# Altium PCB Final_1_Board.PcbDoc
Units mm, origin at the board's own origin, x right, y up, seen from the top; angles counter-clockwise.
Board outline 30.07 x 22.07 mm, 2 copper layers (Top Layer, Bottom Layer), stack 1.671 mm thick; 36 components, 55 nets, 138 pads, 97 vias.
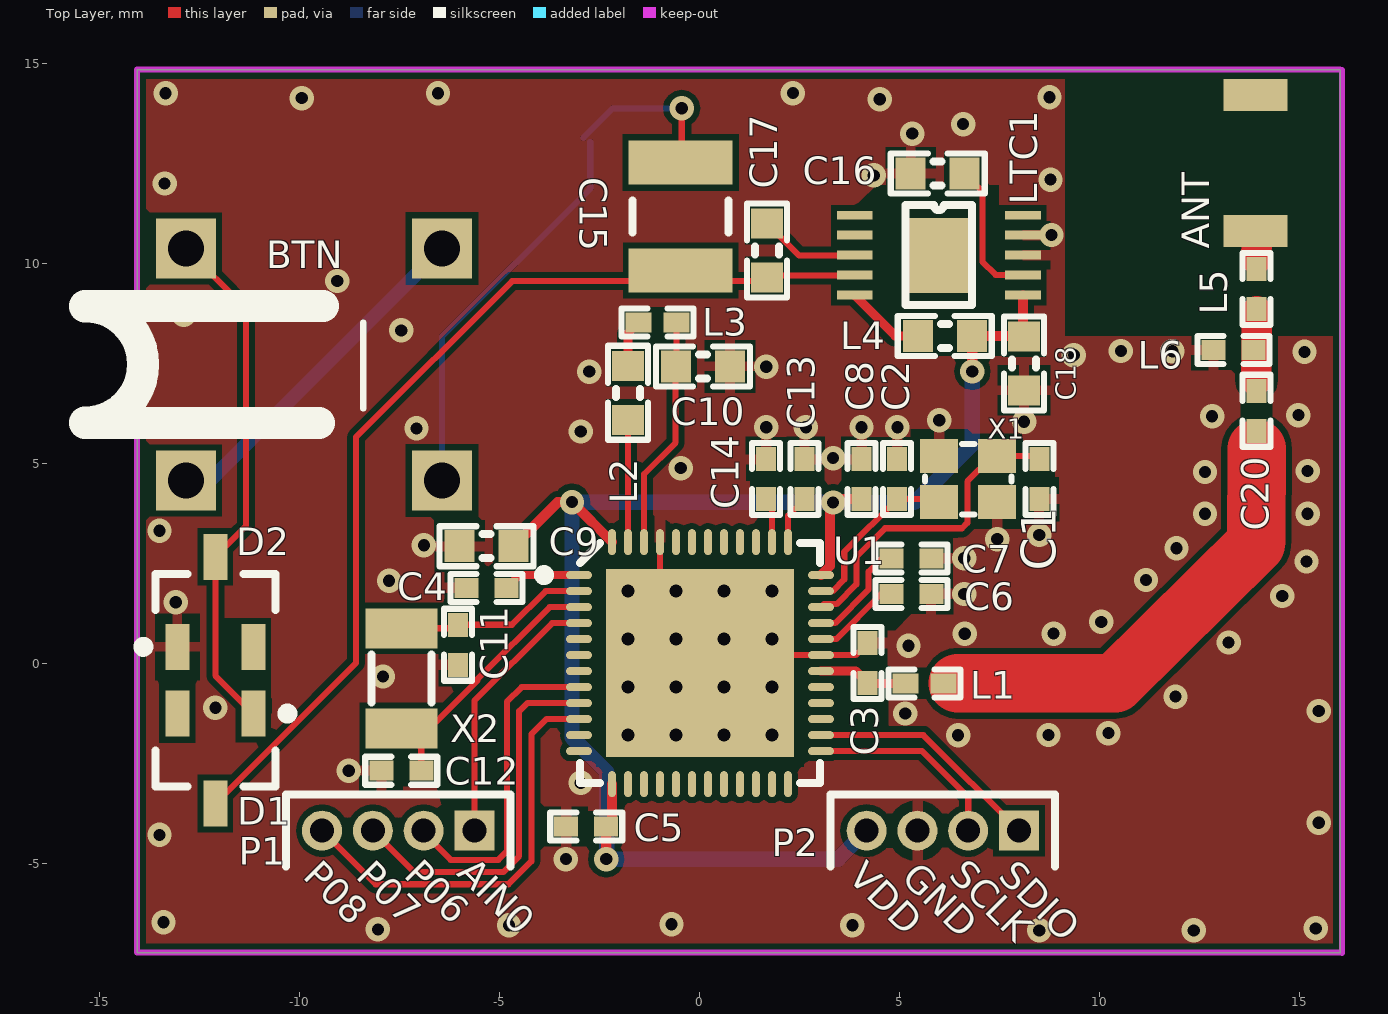
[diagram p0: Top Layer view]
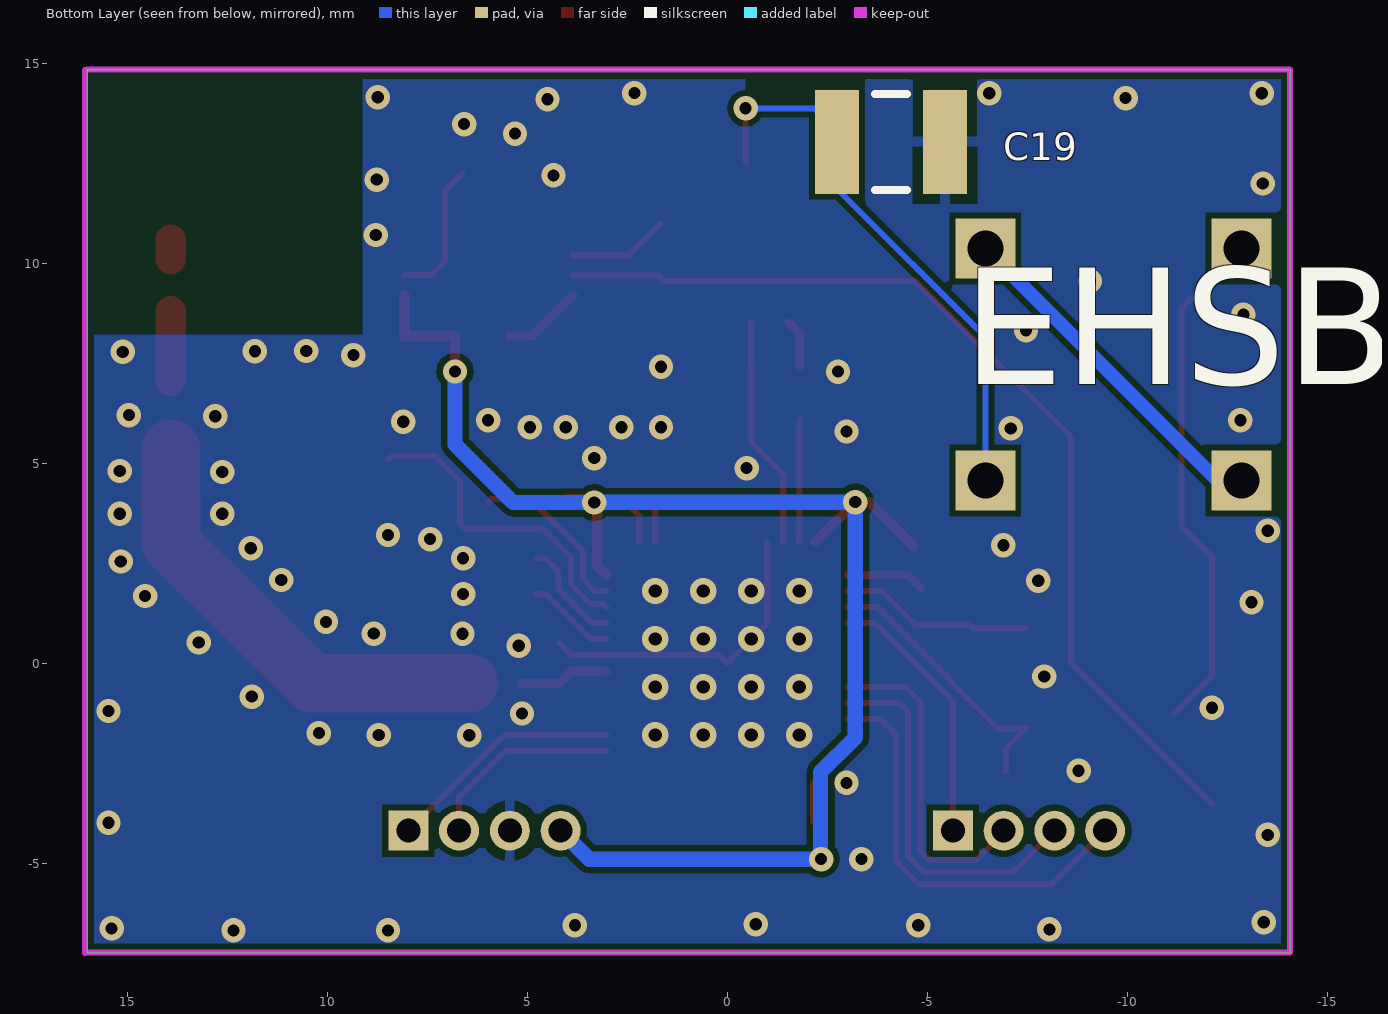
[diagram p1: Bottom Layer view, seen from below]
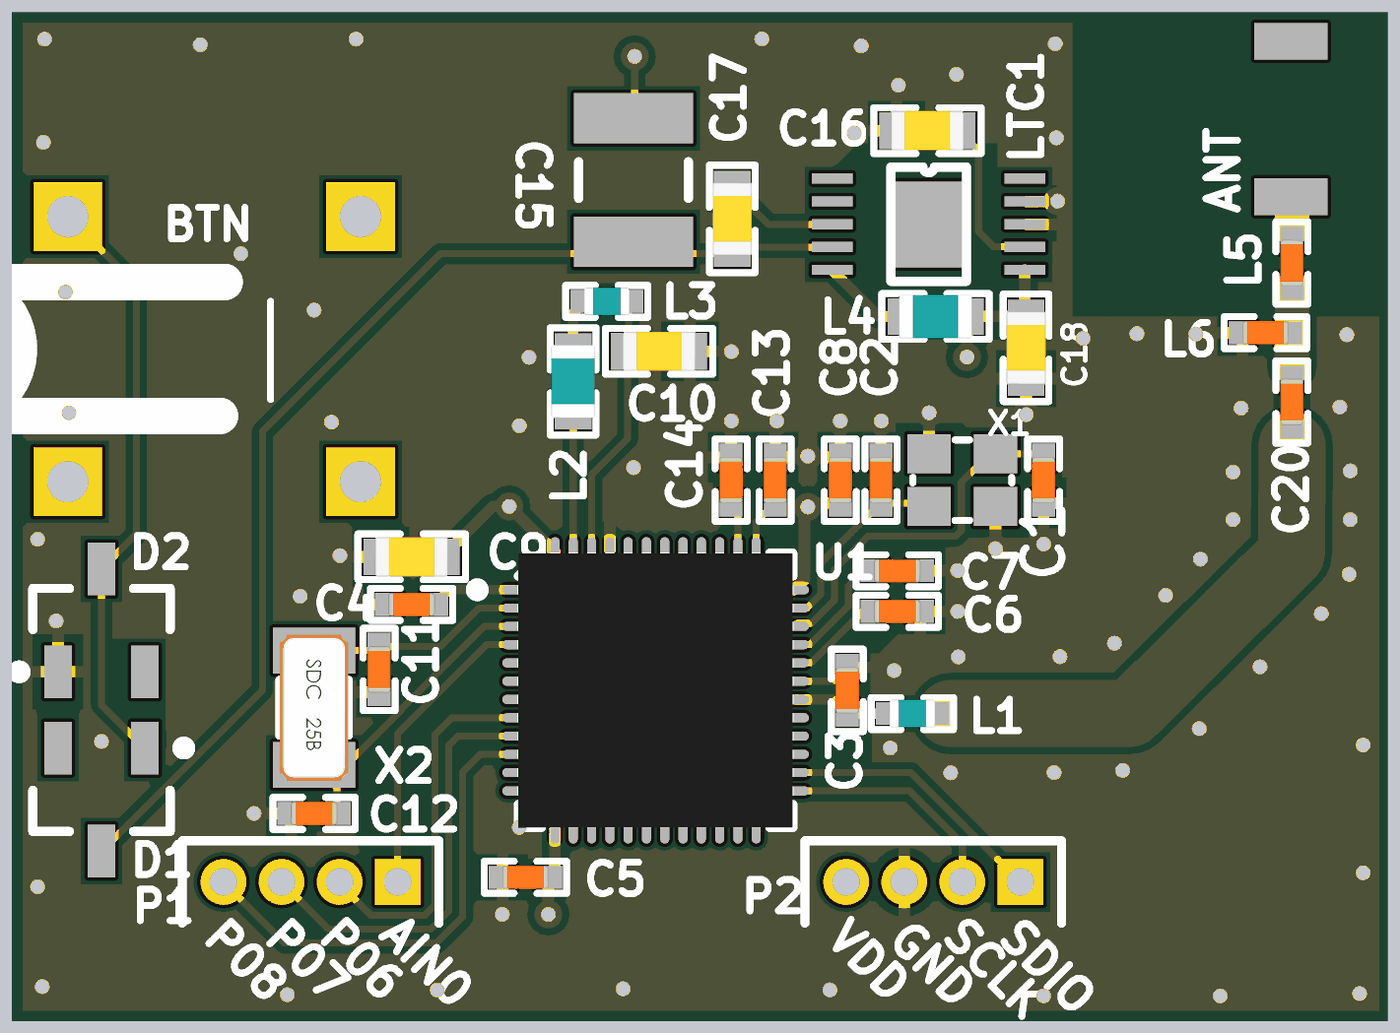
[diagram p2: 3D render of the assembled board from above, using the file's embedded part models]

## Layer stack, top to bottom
Top Solder: solder mask 0.0102, Solder Resist, Dk 3.5
Top Layer: signal copper 0.0356
Dielectric1: core 1.6002, FR-4, Dk 4.8
Bottom Layer: signal copper 0.0356
Bottom Solder: solder mask 0.0102, Solder Resist, Dk 3.5

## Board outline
-14.072,-7.239 -14.072,14.834 16.002,14.834 16.002,-7.239

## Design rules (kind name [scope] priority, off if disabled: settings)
Clearance Polygon_ANT [(InNamedPolygon('Top_Layer-GND')) or (InNamedPolygon('Bottom_Layer-GND')) vs InNet('RF')] p1: gap=0.127 ignorepadtopadclearanceinfootprint=FALSE except(0: Arc-Hole Track-Hole SMDPad-Hole THPad-Hole Via-Hole Fill-Hole Poly-Hole Region-Hole Text-Hole)
Clearance Polygon [(InNamedPolygon('Top_Layer-GND')) or (InNamedPolygon('Bottom_Layer-GND'))] p2: gap=0.254 ignorepadtopadclearanceinfootprint=FALSE except(0: Arc-Hole Track-Hole SMDPad-Hole THPad-Hole Via-Hole Fill-Hole Poly-Hole Region-Hole Text-Hole)
Clearance [All] p3: gap=0.152 ignorepadtopadclearanceinfootprint=FALSE except(0: Arc-Hole Track-Hole SMDPad-Hole THPad-Hole Via-Hole Fill-Hole Poly-Hole Region-Hole Text-Hole)
ComponentClearance [All] p1 off: gap=0.254 collisioncheckmode=3 verticalgap=0.254 showdistances=FALSE
FabricationTestPointUsage TestPointUsage [All] p1: valid=0 allowmultiple=FALSE
FabricationTestpoint Testpoint [All] p1: side=3 testpointundercomponent=TRUE minsize=1.016 maxsize=2.54 preferedsize=1.524 minholesize=0 maxholesize=1.016 preferedholesize=0.813 testpointgrid=0.025 allowsidetop=TRUE allowsidebottom=TRUE usegrid=TRUE gridtolerance=0
Height [All] p1 off: minheight=0 maxheight=25.4 prefheight=12.7
HoleSize [All] p1: absolutevalues=TRUE maxlimit=4.064 minlimit=0.305 maxpercent=80.000 minpercent=20.000
MinimumAnnularRing [All] p1 off: minimumring=0.152
PolygonConnect PolygonConnect_1 [isVia and innet(gnd)] p1: connectstyle=Direct reliefconductorwidth=0.254 reliefentries=4 polygonreliefangle="90 Angle" airgapwidth=0.254
PolygonConnect [All] p2: connectstyle=Relief reliefconductorwidth=0.254 reliefentries=4 polygonreliefangle="90 Angle" airgapwidth=0.254
RoutingVias [All] p1: holewidth=0.406 width=0.813 viastyle="Through Hole" minholewidth=0.254 minwidth=0.254 maxholewidth=0.711 maxwidth=1.27
SilkToSolderMaskClearance SilkscreenOverComponentPads [IsPad] p1: minsilkscreentomaskgap=0.254 clearancetoexposedcopper=TRUE
SolderMaskExpansion [All] p1: expansion=0.076
Width [All] p1: maxlimit=2.54 minlimit=0.152 preferedwidth=0.152
24 further rules are at their usual default settings.

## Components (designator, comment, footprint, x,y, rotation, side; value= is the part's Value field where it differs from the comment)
ANT "Antenna" antenne 13.892,12.497 r90 top (schematic designator E1)
BTN "ZF_button" ZF-button -12.852,10.363 r0 top (schematic designator BTN1)
C1 "12pF" CAPC1005X04L 8.483,4.598 r270 top
C2 "12pF" CAPC1005X04L 4.927,4.598 r90 top
C3 "0.8pF" CAPC1005X04L 4.191,0 r270 top
C4 "100nF" CAPC1005X04L -5.334,1.88 r180 top
C5 "100nF" CAPC1005X04L -2.845,-4.089 r180 top
C6 "N.C." CAPC1005X04L 5.283,1.727 r180 top
C7 "100pF" CAPC1005X04L 5.283,2.616 r0 top
C8 "100nF" CAPC1005X04L 4.038,4.598 r90 top
C9 "4.7µF" CAPC1608X06L -5.334,2.921 r180 top
C10 "1.0µF" CAPC1608X06L 0.076,7.417 r180 top
C11 "12pF" CAPC1005X04L -6.045,0.457 r270 top
C12 "12pF" CAPC1005X04L -7.468,-2.692 r180 top
C13 "12pF" CAPC1005X04L 2.616,4.598 r90 top
C14 "12pF" CAPC1005X04L 1.651,4.598 r90 top
C15 "47µF" C1210 -0.483,11.162 r270 top
C16 "4.7µF" CAPC1608X06L 5.944,12.243 r0 top
C17 "1µF" CAPC1608X06L 1.676,10.312 r270 top
C18 "47µF" CAPC1608X06L 8.1,7.493 r90 top
C19 "220µF" C1210 -4.093,13.03 r0 bottom
C20 "Cap" CAPC1005X04L 13.911,6.307 r90 top value=12pF
D1 "Diode 1N4004" SOT-23_N -12.116,-2.388 r270 top
D2 "Diode 1N4004" SOT-23_N -12.116,1.53 r90 top
L1 "3.9nH" INDC1005X04L 5.613,-0.508 r0 top
L2 "10µH" INDC1608X06L -1.803,6.756 r270 top
L3 "15nH" INDC1005X04L -1.067,8.509 r180 top
L4 "10µH" INDC1608X06L 6.12,8.179 r0 top
L5 "3.3nH" CAPC1005X04L 13.912,9.347 r90 top value=3.9nH
L6 "2.7nH" CAPC1005X04L 13.335,7.823 r180 top value=3.9nH
LTC1 "2x5 Pin" "MSOP10 - duplicate1" 3.864,11.197 r0 top
P1 "MHDR1X4" MHDR1X4 -5.639,-4.191 r180 top
P2 "MHDR1X4" MHDR1X4 7.976,-4.191 r180 top
U1 "nRF52832-QFAA" QFN40P600X600X90-48N 0,0 r0 top locked
X1 "32MHz" BT-XTAL_2016 6.705,4.598 r180 top
X2 "32.768kHz" XTAL_3215 -7.468,-0.381 r270 top

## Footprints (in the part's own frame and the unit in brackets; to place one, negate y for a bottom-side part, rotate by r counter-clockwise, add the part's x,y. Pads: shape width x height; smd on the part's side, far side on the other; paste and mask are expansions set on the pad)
antenne [mm]
  rect 0.8x1.6 smd: 1(-1.7,0) 2(1.7,0)
BT-XTAL_2016 [mm] "Crystal 2.0 x 1.6 mm"
  rect 0.95x0.85 smd: 1(-0.725,-0.575) 2(0.725,-0.575) 3(0.725,0.575) 4(-0.725,0.575)
  silkscreen extent -1.08,-0.88 1.08,0.88
C1210 [mm] "Chip Capacitor, Body 3.2x2.5mm, IPC High Density"
  rect 1.1x2.6 smd: 1(-1.35,0) 2(1.35,0)
  silkscreen extent -0.4,-1.2 0.4,1.2, body extent -1.7,-1.35 1.7,1.35, height 1.3
CAPC1005X04L [mm] "Chip Capacitor, 2-Leads, Body 1.0x0.5mm, IPC High Density"
  rect 0.6x0.5 smd: 1(-0.5,0) 2(0.5,0)
  silkscreen extent -0.9,-0.35 0.9,0.35, body extent -0.51,-0.25 0.51,0.25, height 0.5
CAPC1608X06L [mm] "Chip Capacitor, 2-Leads, Body 1.6x0.8mm, IPC High Density"
  rect 0.75x0.8 smd: 1(-0.675,0) 2(0.675,0)
  silkscreen extent -1.17,-0.5 1.17,0.5, body extent -0.8,-0.43 0.8,0.43, height 0.8
INDC1005X04L [mm] "Chip Inductor, 2-Leads, Body 1.0x0.5mm, IPC High Density"
  rect 0.65x0.5 smd: 1(-0.475,0) 2(0.475,0)
  silkscreen extent -0.9,-0.35 0.9,0.35, body extent -0.5,-0.3 0.5,0.3, height 0.5
INDC1608X06L [mm] "Chip Inductor, 2-Leads, Body 1.6x0.8mm, IPC High Density"
  rect 0.75x0.8 smd: 1(-0.675,0) 2(0.675,0)
  silkscreen extent -1.18,-0.5 1.17,0.5, body extent -0.8,-0.48 0.8,0.48, height 0.8
MHDR1X4 [mm] "Connector; Header; 4 Position"
  rect 1x1 hole 0.6: 1(0,0)
  round 1 hole 0.6: 2(1.27,0) 3(2.54,0) 4(3.81,0)
  silkscreen extent -0.9,-0.9 4.71,0.9
"MSOP10 - duplicate1" [mm]
  rect 0.889x0.22 smd: 1(0,0) 2(0,-0.5) 3(0,-1) 4(0,-1.5) 5(0,-2) 6(4.211,-2) 7(4.211,-1.5) 8(4.211,-1) 9(4.211,-0.5) 10(4.211,0)
  rect 1.68x1.88 smd: 26(2.105,-1.006)
  silkscreen extent 1.28,-2.25 2.93,0.25
QFN40P600X600X90-48N [mm] "QFN, 48-Leads, Body 6,0x6,0mm (max), Pitch 0,40mm, IPC Medium Density"
  oval 0.65x0.2 smd: 1(-3.025,2.2) 2(-3.025,1.8) 3(-3.025,1.4) 4(-3.025,1) 5(-3.025,0.6) 6(-3.025,0.2) 7(-3.025,-0.2) 8(-3.025,-0.6) 9(-3.025,-1) 10(-3.025,-1.4) 11(-3.025,-1.8) 12(-3.025,-2.2) 25(3.025,-2.2) 26(3.025,-1.8) 27(3.025,-1.4) 28(3.025,-1) 29(3.025,-0.6) 30(3.025,-0.2) 31(3.025,0.2) 32(3.025,0.6) 33(3.025,1) 34(3.025,1.4) 35(3.025,1.8) 36(3.025,2.2)
  oval 0.2x0.65 smd: 13(-2.2,-3.025) 14(-1.8,-3.025) 15(-1.4,-3.025) 16(-1,-3.025) 17(-0.6,-3.025) 18(-0.2,-3.025) 19(0.2,-3.025) 20(0.6,-3.025) 21(1,-3.025) 22(1.4,-3.025) 23(1.8,-3.025) 24(2.2,-3.025) 37(2.2,3.025) 38(1.8,3.025) 39(1.4,3.025) 40(1,3.025) 41(0.6,3.025) 42(0.2,3.025) 43(-0.2,3.025) 44(-0.6,3.025) 45(-1,3.025) 46(-1.4,3.025) 47(-1.8,3.025) 48(-2.2,3.025)
  rect 4.7x4.7 smd: 49(0,0)
  silkscreen extent -4.02,-3 3,3, body extent -3.02,-3.02 3.02,3.02, height 0.86
SOT-23_N [mm] "SOT23, 3-Leads, Body 2.9x1.3mm, Pitch 0.95mm, Lead Span 2.5mm, IPC Medium Density"
  rect 1.15x0.6 smd: 1(-1.125,0.95) 2(-1.125,-0.95) 3(1.125,0)
  silkscreen extent -1.25,-1.5 0.7,1.93, body extent -0.7,-1.5 0.7,1.5, height 1.1
XTAL_3215 [mm] "XTAL SMD 3.2 x 1.5 mm"
  rect 1x1.8 smd: 1(-1.25,0) 2(1.25,0)
  silkscreen extent -0.6,-0.75 0.6,0.75, body extent -1.6,-0.75 1.6,0.75, height 0.81
ZF-button [mm]
  rect 1.5x1.5 hole 0.9: 1(0,0) 2(0,-5.8) 3(6.4,-5.8) 4(6.4,0)
  silkscreen extent -2.52,-4.36 3.43,-1.43

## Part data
ANT: "Generic Antenna"
C1 C2 C11 C12 C13 C14: library part C0402-12p, "Capacitor, NP0, ±2%"
C3: library part C0402-0.8p, "Capacitor, NP0, ±5%"
C4 C5 C8: library part C0402-100n, "Capacitor, X7R, ±10%"
C6: library part C0402-N.C., "Not mounted"
C7: library part C0402-100p, "Capacitor, NP0, ±5%"
C9: library part C0603-4µ7, "Capacitor, X5R, ±10%"
C10: library part C0603-1µ0, "Capacitor, X7R, ±10%"
C15 C16 C17 C18 C19: "Capacitor, X5R, ±10%", Part Number=C0603-4µ7
C20: "Capacitor"
D1 D2: "1 Amp General Purpose Rectifier"
L1 L5 L6: library part L0402-3n9, "High frequency chip inductor ±5%", Manufacturer=Murata, Manufacturer Part Number=LQP15MN3N9B02D, Supplier part number=490-1131-1-ND
L2: library part L0603-10µ, "Chip inductor, IDC,min = 50 mA, ±20%", 2nd source part number=178-6105, Manufacturer="Taiyo Yuden", Manufacturer Part Number=LBMF1608T100K, Supplier part number=587-1714-1-ND
L3: library part L0402-15n, "High frequency chip inductor ±10%", 2nd source part number=658-1328, Manufacturer="Taiyo Yuden", Manufacturer Part Number=HK100515NJ-T, Supplier part number=587-1521-1-ND
L4: "Chip inductor, IDC,min = 50 mA, ±20%", 2nd source part number=178-6105, Manufacturer="Taiyo Yuden", Manufacturer Part Number=LBMF1608T100K, Part Number=L0603-10µ, Supplier part number=587-1714-1-ND
P1 P2: "Header, 4-Pin"
U1: "Multi-protocol Bluetooth Low Energy, ANT and 2.4GHz proprietary system-on-chip", Manufacturer="Nordic Semiconductor"
X1: library part XTAL_SMD2016_32MHz_8pF_General, "XTAL SMD 2016, 32MHz, Cl=8pF, Total Tol: ±40ppm"
X2: library part XTAL_SMD3215_32.768kHz_9pF_General, "XTAL SMD 3215, 32.768kHz, Cl=9pF, Total Tol: ±50ppm"

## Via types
v1: diameter 0.61, hole 0.305, Top Layer to Bottom Layer, tented both sides, 81 vias
v2: diameter 0.66, hole 0.33, Top Layer to Bottom Layer, tented both sides, 16 vias

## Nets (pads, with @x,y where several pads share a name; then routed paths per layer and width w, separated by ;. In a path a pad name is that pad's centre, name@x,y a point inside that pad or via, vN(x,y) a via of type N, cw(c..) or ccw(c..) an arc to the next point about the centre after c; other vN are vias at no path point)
DEC1: C4.1 U1.1 | length 1.9
  Top Layer w0.203: C4.1 -4.514,2.2 U1.1
DEC2: C6.2 U1.32 | length 2.2
  Top Layer w0.152: U1.32 3.408,0.6 4.521,1.713 4.521,1.727 C6.2
DEC3: C7.1 U1.33 | length 2.7
  Top Layer w0.152: U1.33 3.377,1 4.216,1.84 4.216,2.286 4.547,2.616 C7.1
DEC4: C10.2 L3.1 U1.46 | length 5.8
  Top Layer w0.152: U1.46 -1.4,4.721 -0.61,5.512 -0.61,7.406 C10.2 -0.592,7.424 L3.1
GND: C1.2 C2.2 C3.1 C4.2 C5.2 C6.1 C7.2 C8.2 C9.2 C10.1 C11.2 C12.2 C13.2 C14.2 C16.1 C18.1 C19.1 D2.1 L6.2 LTC1.8 LTC1.9 P2.3 U1.31 U1.45 U1.49 X1.2 X1.4 | length 7.8
  Top Layer w0.152: U1.45 -1,1 v2(-0.6,0.6) U1.49 0.2,0.2 U1.31 3.891,0.2 C3.1
  other v1: 8.484,-6.684 12.344,-6.684 -8.052,-6.659 15.392,-6.633 -4.775,-6.557 3.81,-6.553 -0.711,-6.528 -13.411,-6.481 -3.353,-4.902 -13.513,-4.296 15.469,-3.992 -2.98,-2.997 -8.782,-2.692 6.452,-1.803 8.712,-1.8 10.211,-1.753 5.131,-1.263 15.469,-1.198 -12.116,-1.118 11.887,-0.838 -7.925,-0.336 5.213,0.432 13.214,0.513 6.619,0.732 8.839,0.737 10.033,1.03 -13.106,1.518 14.554,1.676 6.604,1.727 -7.772,2.057 11.151,2.077 15.164,2.54 6.604,2.621 11.913,2.87 -6.903,2.946 7.43,3.099 8.484,3.2 -13.513,3.305 12.624,3.734 15.189,3.734 12.624,4.775 15.189,4.801 -0.483,4.873 3.327,5.123 -2.98,5.787 -7.087,5.867 1.657,5.893 2.648,5.893 4.039,5.893 4.934,5.893 8.103,6.031 -12.827,6.071 5.98,6.071 12.802,6.172 14.961,6.198 -2.769,7.286 1.657,7.41 9.347,7.699 15.113,7.779 10.524,7.801 11.811,7.794 -7.468,8.317 -12.903,8.712 -9.068,9.55 8.788,10.701 -13.386,11.989 8.763,12.086 4.343,12.192 5.309,13.237 6.579,13.474 4.495,14.097 -9.957,14.122 8.738,14.144 -13.36,14.246 -6.549,14.246 2.322,14.249
  other v2: -1.8,-1.8 -0.6,-1.8 0.6,-1.8 1.8,-1.8 -1.8,-0.6 -0.6,-0.6 0.6,-0.6 1.8,-0.6 -1.8,0.6 0.6,0.6 1.8,0.6 -1.8,1.8 -0.6,1.8 0.6,1.8 1.8,1.8
NetBTN1_1: BTN.1 D1.1 D2.3 | length 13
  Top Layer w0.152: BTN.1 -11.354,8.865 -11.354,3.417 D2.3 -12.116,-0.313 D1.1
NetBTN1_2: BTN.2 BTN.4 | length 8.8
  Bottom Layer w0.152: BTN.2 BTN.2@-12.252,4.563
  Bottom Layer w0.35: BTN.2@-12.252,4.563 BTN.4
NetBTN1_3: BTN.3 C15.1 C19.2 | length 14.1
  Top Layer w0.152: C15.1 -0.457,12.538 v1(-0.457,13.868)
  Bottom Layer w0.152: BTN.3 -6.452,8.152 -2.743,11.861 C19.2 ; C19.2@-2.917,13.132 -2.181,13.868 v1(-0.457,13.868)
NetC3_2: C3.2 L1.1 U1.30 | length 2.2
  Top Layer w0.229: U1.30 3.891,-0.2 C3.2 4.199,-0.508 L1.1
NetC11_1: C11.1 U1.2 X2.1 | length 4.8
  Top Layer w0.152: X2.1 -6.133,0.869 C11.1 -4.704,0.957 -3.861,1.8 U1.2
NetC12_1: C12.1 U1.3 X2.2 | length 7
  Top Layer w0.152: C12.1 -6.968,-2.131 X2.2 -6.76,-1.631 -5.567,-0.437 -5.567,-0.41 -3.756,1.4 U1.3
NetC15_2: C15.2 C17.2 D1.3 LTC1.4 | length 24.8
  Top Layer w0.152: D1.3 -8.596,0.007 -8.596,5.653 -4.699,9.55 1.589,9.55 C17.2 1.73,9.691 LTC1.4@3.864,9.691
NetC16_2: C16.2 LTC1.7 | length 3.5
  Top Layer w0.152: C16.2 7.061,11.8 7.061,10.033 7.391,9.703 8.064,9.703 LTC1.7@8.075,9.691
NetC17_1: C17.1 LTC1.3 | length 2.5
  Top Layer w0.152: C17.1 2.472,10.191 LTC1.3@3.864,10.191
NetC20_2: C20.2 L5.1 L6.1 | length 1.7
  Top Layer w0.762: C20.2@13.911,7.061 13.915,7.823 L5.1@13.919,8.795
NetE1_1: ANT.1 L5.2 | length 0.5
  Top Layer w0.762: L5.2@13.912,10.098 ANT.1@13.919,10.584
NetL2_1: L2.1 L3.2 | length 1.2
  Top Layer w0.229: L2.1 -1.803,8.247 L3.2
NetL2_2: L2.2 U1.47 | length 3.1
  Top Layer w0.152: L2.2 -1.803,3.028 U1.47
NetL4_1: L4.1 LTC1.5 | length 2
  Top Layer w0.229: LTC1.5@3.864,9.191 4.877,8.179 L4.1
P0.02/AIN0: P1.1 U1.4 | length 6.7
  Top Layer w0.152: P1.1 -5.639,-0.941 -3.698,1 U1.4
P0.03/AIN1: U1.5
P0.04/AIN2: U1.6
P0.05/AIN3: U1.7
P0.06: P1.2 U1.8 | length 8.2
  Top Layer w0.152: P1.2 -6.909,-4.244 -6.233,-4.92 -5.044,-4.92 -4.826,-4.701 -4.826,-0.966 -4.46,-0.6 U1.8
P0.07: P1.3 U1.9 | length 9.5
  Top Layer w0.152: P1.3 -7.145,-5.224 -4.918,-5.224 -4.521,-4.828 -4.521,-1.206 -4.316,-1 U1.9
P0.08: P1.4 U1.10 | length 10.5
  Top Layer w0.152: P1.4 -8.111,-5.529 -4.792,-5.529 -4.216,-4.954 -4.216,-1.778 -3.838,-1.4 U1.10
P0.09: U1.11
P0.10: U1.12
P0.11: U1.14
P0.12: U1.15
P0.13: U1.16
P0.14: U1.17
P0.15: U1.18
P0.16: U1.19
P0.17: U1.20
P0.18: U1.21
P0.19: U1.22
P0.20: U1.23
P0.21: U1.24
P0.22: U1.27
P0.23: U1.28
P0.24: U1.29
P0.25: C13.1 U1.37 | length 1.2
  Top Layer w0.152: U1.37 2.2,3.682 C13.1
P0.26: C14.1 U1.38 | length 1.1
  Top Layer w0.152: C14.1 1.8,3.948 U1.38
P0.27: U1.39
P0.28/AIN4: U1.40
P0.29/AIN5: U1.41
P0.30/AIN6: U1.42
P0.31/AIN7: U1.43
RF: C20.1 L1.2 | length 11.1
  Top Layer w1.466: 6.452,-0.508 10.338,-0.508 ; 10.386,-0.501 13.892,2.974 ; 13.906,3.048 13.917,5.36
SWDCLK: P2.2 U1.25 | length 5
  Top Layer w0.152: U1.25 5.554,-2.2 6.706,-3.352 P2.2
SWDIO: P2.1 U1.26 | length 5.9
  Top Layer w0.152: U1.26 5.585,-1.8 P2.1
VDD_NRF: C5.1 C8.1 C9.1 C18.2 L4.2 LTC1.6 P2.4 U1.13 U1.36 U1.48 | length 39.7
  Top Layer w0.254: C9.1 -3.557,4.023 v1(-3.2,4.023) -3.198,4.023 U1.48 ; v1(-2.345,-4.902) C5.1 -2.2,-3.945 U1.13 ; U1.36 3.251,2.426 3.251,3.937 v1(3.327,4.013) 3.412,4.098 C8.1 ; v1(6.807,7.29) 6.807,8.166 L4.2 8.09,8.179 8.075,8.193 LTC1.6@8.075,9.191
  Bottom Layer w0.381: P2.4 3.454,-4.902 v1(-2.345,-4.902) -2.332,-4.889 -2.332,-2.729 -3.2,-1.861 v1(-3.2,4.023) 3.318,4.023 v1(3.327,4.013) 5.359,4.013 6.807,5.461 v1(6.807,7.29)
XC1: C1.1 U1.34 X1.1 | length 8.1
  Top Layer w0.152: U1.34 3.096,1.471 3.417,1.471 3.912,1.966 3.912,2.651 4.63,3.369 6.55,3.369 6.684,3.503 6.684,4.543 7.314,5.173 X1.1 8.408,5.173 C1.1
XC2: C2.1 U1.35 X1.3 | length 4.3
  Top Layer w0.152: U1.35 3.315,1.8 3.607,2.092 3.607,2.777 C2.1 5.905,4.098 X1.3
pads on no net: ANT.2 D1.2 D2.2 LTC1.1 LTC1.2 LTC1.10 LTC1.26 U1.44

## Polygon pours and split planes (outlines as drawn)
GND on Bottom Layer "Bottom Layer-GND" (solid, pour order 2): -13.995,14.732 -13.97,14.757 9.119,14.757 9.119,8.23 9.144,8.204 15.875,8.204 15.926,8.153 15.926,-7.264 -13.919,-7.264 -14.046,-7.137 -13.995,-7.087
GND on Top Layer "Top Layer-GND" (solid, pour order 4): -13.995,14.757 9.119,14.757 9.119,8.173 15.926,8.173 15.926,-7.239 -13.919,-7.239 -13.995,-7.163

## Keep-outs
Keep-Out Layer:
  lines w0.152: 16.002,14.834 -14.072,14.834 -14.072,-7.239 16.027,-7.239 ; 16.053,-7.243 16.053,14.83

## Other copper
Top Layer:
  pour cut-out: 5.385,1.321 4.877,0.813 4.541,0.813
  pour cut-out: -10.693,-0.889 -10.713,-0.869 -10.713,1.132 -12.079,1.132 -11.963,1.016 -11.963,-0.42 -11.536,-0.42 -10.693,-1.263
  pour cut-out: 7.798,8.382 7.478,8.702 7.478,11.963 4.42,11.963 3.962,11.506 4.343,11.125 4.343,8.644 5.317,7.671 7.747,7.671 7.747,9.474 7.696,9.525
  pour cut-out: 4.724,-0.818 4.724,-1.561 4.659,-1.626
  pour cut-out: -6.604,-3.042 -6.388,-3.258 -6.388,-3.856
Bottom Layer:
  pour cut-out: 0.624,13.635
  pour cut-out: -0.508,14.453 -0.508,14.757 -0.445,14.694 -0.445,14.246

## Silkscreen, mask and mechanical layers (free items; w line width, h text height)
Top Overlay:
  lines w0.152: -8.418,6.365 -8.418,8.509
  text "AIN0" at -6.11,-5.283 h0.69 r315
  text "P06" at -7.434,-5.334 h0.69 r315
  text "SCLK" at 6.198,-5.334 h0.69 r315
  text "P08" at -9.957,-5.359 h0.69 r315
  text "P07" at -8.627,-5.359 h0.69 r315
  text "SDIO" at 7.425,-5.359 h0.69 r315
  text "VDD" at 3.666,-5.385 h0.69 r315
  text "GND" at 5.012,-5.41 h0.69 r315
Bottom Overlay:
  text "EHSB" at -5.893,6.002 h5

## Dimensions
18.466,14.808 to 18.186,-7.214 on Top Layer
-14.021,16.307 to 16.027,16.129 on Top Layer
